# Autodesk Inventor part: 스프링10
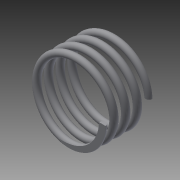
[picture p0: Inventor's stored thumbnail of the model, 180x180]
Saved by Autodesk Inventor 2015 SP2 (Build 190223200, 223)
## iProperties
Created: 2015-06
Part Number: 스프링10
Material: 일반
Document SubType Name: Modeling
Designer: AMC
Density: 1 g/cm^3
Appearance: 기본값
Mass: 0.344274 g
Surface Area: 9.40933 cm^2
Volume: 0.344274 cm^3
Author: AMC
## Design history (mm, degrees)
sketch "스케치1"
  geometry: L1 (0, 0)-(8, 0); L2 (8, 0)-(8, 10.5); L3 (8, 10.5)-(0, 10.5); L4 (0, 10.5)-(0, 0); C1 r 0.75 at (8, 0)
  constraints: 8 end point, 2 parallel, 1 centre point, 1 coincident, 1 horizontal, 1 perpendicular
  dimensions: "d0" = 8 distance of L3.end L2.end; "d1" = 10.5 distance of L2.end L1.end (derived); "d2" = 10.5 distance between parallel lines of L3 L1 (derived); "d3" = 1.5 diameter of C1
feature "코일1" sketch "스케치1" pitch "d4" = 10; turns "d6" = 4; dims "d5" = 10.5 (= d1), "d7" = 0, angle "d8" = 90 deg, angle "d9" = 90 deg, "d10" = 0, "d11" = 0
sketch "스케치2"
  geometry: L1 (2.971, 0)-(-21.019, 0); L2 (-21.019, 0)-(-21.019, -29.714); L3 (-21.019, -29.714)-(2.971, -29.714); L4 (2.971, -29.714)-(2.971, 0); L5 (4.181, 10.5)-(-23.875, 10.5); L6 (-23.875, 10.5)-(-23.875, 42.277); L7 (-23.875, 42.277)-(4.181, 42.277); L8 (4.181, 42.277)-(4.181, 10.5); C1 r 0.75 at (0, 0) reference; C2 r 0.75 at (0, 10.5) reference; 8 further points
  constraints: 16 end point, 4 parallel, 2 horizontal, 2 perpendicular, 1 point on line, 7 other
  dimensions: "d12" = 10.5 distance between parallel lines of L1 L5 (= d1)
extrude "돌출1" cut sketch "스케치2" stored distance "d13" = 123; taper "d14" = 0 deg
node "솔리드1"
node "절단 모서리 투영1"
